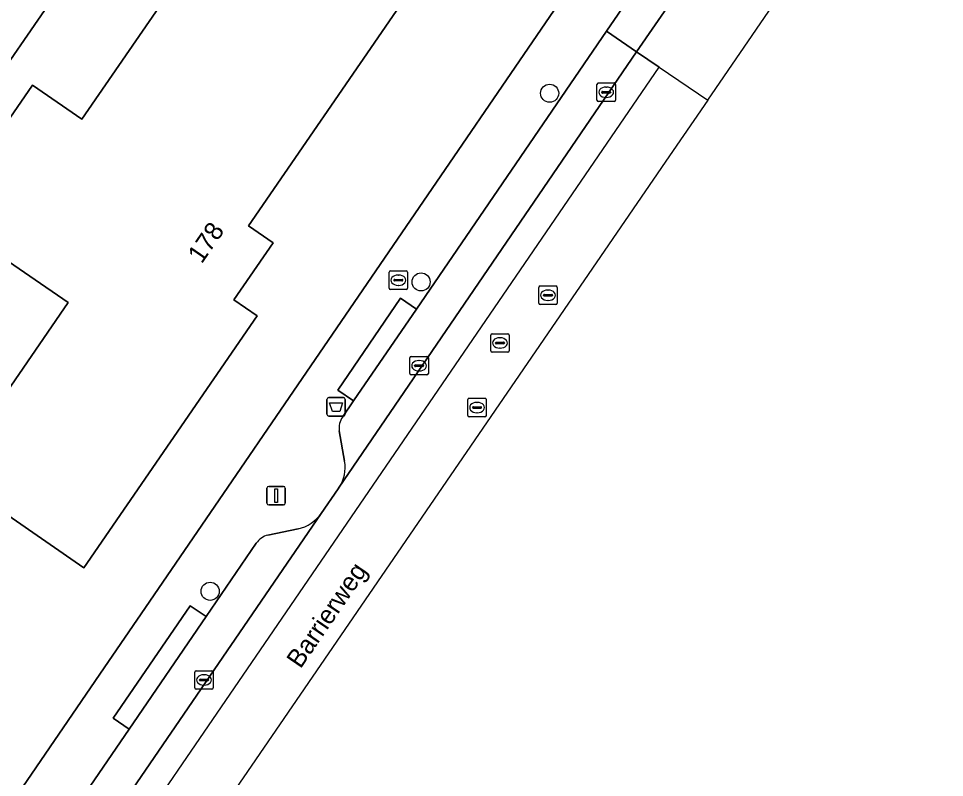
# Model space of a CAD drawing. Extents: x 159664 to 160323, y 385312 to 386115.
# Drawn here: x 160197.9 to 160248, y 385585.5 to 385626.6 of the extents above; entities that cross this region are included whole.
import ezdxf

# ---------------------------------------------------------------- set-up
doc = ezdxf.new("R2010")
doc.units = 0
for name, color, linetype in [('IMGEO_Afvalbak', 7, 'Continuous'), ('IMGEO_Boom', 7, 'Continuous'), ('IMGEO_Brandkraan', 7, 'Continuous'), ('IMGEO_Erf', 7, 'Continuous'), ('IMGEO_Kolk', 7, 'Continuous'), ('IMGEO_Lichtmast', 7, 'Continuous'), ('IMGEO_Openbare_ruimte_label', 7, 'Continuous'), ('IMGEO_Pand', 7, 'Continuous'), ('IMGEO_Pand_nummerreeks', 7, 'Continuous'), ('IMGEO_Parkeervlak_open', 7, 'Continuous'), ('IMGEO_Rijbaan_lokaal_gesloten', 7, 'Continuous'), ('IMGEO_Rijbaan_lokaal_open', 7, 'Continuous'), ('IMGEO_Rioolput', 7, 'Continuous'), ('IMGEO_Voetpad_open', 7, 'Continuous')]:
    doc.layers.add(name, color=color, linetype=linetype)

msp = doc.modelspace()

# ---------------------------------------------------------------- linework, layer by layer
at = {"layer": 'IMGEO_Afvalbak'}
for p, q in [((160214.622, 385605.183), (160214.622, 385605.983)), ((160214.622, 385605.983), (160214.622, 385605.183)), ((160214.722, 385606.083), (160215.512, 385606.083)), ((160215.512, 385606.083), (160214.722, 385606.083)), ((160215.612, 385605.983), (160215.612, 385605.183)), ((160215.612, 385605.183), (160215.612, 385605.983)), ((160215.512, 385605.083), (160214.722, 385605.083)), ((160214.722, 385605.083), (160215.512, 385605.083))]:
    msp.add_line(p, q, dxfattribs=at)
msp.add_lwpolyline([(160214.765, 385605.797), (160215.469, 385605.797), (160215.32, 385605.327), (160214.914, 385605.327), (160214.765, 385605.797)], dxfattribs=at)
for centre, start, end in [((160214.722, 385605.983), 90, 180), ((160214.722, 385605.983), 90, 180), ((160215.512, 385605.983), 0, 90), ((160215.512, 385605.983), 360, 90), ((160214.722, 385605.183), 180, 270), ((160214.722, 385605.183), 180, 270), ((160215.512, 385605.183), 270, 0), ((160215.512, 385605.183), 270, 0)]:
    msp.add_arc(centre, 0.1, start, end, dxfattribs=at)
at = {"layer": 'IMGEO_Boom'}
for centre in [(160226.666, 385622.529), (160219.712, 385612.329), (160208.305, 385595.607)]:
    msp.add_circle(centre, 0.489, dxfattribs=at)
at = {"layer": 'IMGEO_Brandkraan'}
for p, q in [((160217.983, 385611.998), (160217.983, 385612.85)), ((160218.058, 385612.924), (160218.91, 385612.924)), ((160218.285, 385612.467), (160218.683, 385612.467)), ((160218.471, 385612.704), (160218.496, 385612.704)), ((160218.984, 385612.85), (160218.984, 385611.998)), ((160218.242, 385612.418), (160218.242, 385612.43)), ((160218.68, 385612.381), (160218.282, 385612.381)), ((160218.494, 385612.144), (160218.469, 385612.144)), ((160218.726, 385612.43), (160218.726, 385612.418)), ((160218.91, 385611.924), (160218.058, 385611.924))]:
    msp.add_line(p, q, dxfattribs=at)
for points in [[(160217.983, 385611.998), (160217.983, 385612.85)], [(160218.058, 385612.924), (160218.91, 385612.924)], [(160218.984, 385612.85), (160218.984, 385611.998)], [(160218.91, 385611.924), (160218.058, 385611.924)]]:
    msp.add_lwpolyline(points, dxfattribs=at)
for centre, radius, start, end in [((160218.06, 385612.848), 0.0765, 91.552, 178.448), ((160218.06, 385612.848), 0.0765, 91.552, 178.448), ((160218.282, 385612.427), 0.0403, 85.8775, 175.7526), ((160218.687, 385612.429), 0.0386, 1.7309, 96.639), ((160218.908, 385612.848), 0.0765, 1.552, 88.448), ((160218.908, 385612.848), 0.0765, 1.552, 88.448), ((160218.06, 385612), 0.0765, 181.552, 268.448), ((160218.06, 385612), 0.0765, 181.552, 268.448), ((160218.279, 385612.417), 0.0366, 178.938, 274.7102), ((160218.683, 385612.424), 0.043, 264.8664, 352.4533), ((160218.908, 385612), 0.0765, 271.552, 358.448), ((160218.908, 385612), 0.0765, 271.552, 358.448)]:
    msp.add_arc(centre, radius, start, end, dxfattribs=at)
for centre, major_axis, ratio, start_param, end_param in [((160218.47, 385612.424), (-0.387, 0.002), 0.722429, 4.712389, 7.853982), ((160218.495, 385612.424), (-0.39, 0.002), 0.717154, 1.570796, 4.712389)]:
    msp.add_ellipse(centre, major_axis=major_axis, ratio=ratio, start_param=start_param, end_param=end_param, dxfattribs=at)
at = {"layer": 'IMGEO_Erf'}
for points in [[(160178.275, 385555.964), (160202.573, 385591.477), (160204.804, 385594.737), (160228.781, 385629.782), (160232.101, 385634.648), (160226.352, 385638.579), (160210.37, 385615.359), (160211.709, 385614.437), (160209.591, 385611.36), (160210.845, 385610.497), (160201.475, 385596.884), (160197.356, 385599.719)], [(160194.203, 385601.89), (160200.619, 385611.212), (160193.817, 385615.893), (160198.69, 385622.972), (160201.368, 385621.129), (160209.201, 385632.509), (160205.097, 385635.362), (160196.943, 385623.519)]]:
    msp.add_lwpolyline(points, dxfattribs=at)
at = {"layer": 'IMGEO_Kolk'}
for p, q in [((160229.224, 385622.157), (160229.224, 385623.009)), ((160229.299, 385623.083), (160230.151, 385623.083)), ((160230.225, 385623.009), (160230.225, 385622.157)), ((160229.483, 385622.577), (160229.483, 385622.589)), ((160229.921, 385622.54), (160229.523, 385622.54)), ((160229.526, 385622.626), (160229.924, 385622.626)), ((160229.712, 385622.863), (160229.737, 385622.863)), ((160229.967, 385622.589), (160229.967, 385622.577)), ((160230.151, 385622.083), (160229.299, 385622.083)), ((160229.735, 385622.303), (160229.71, 385622.303)), ((160219.105, 385607.375), (160219.105, 385608.227)), ((160219.18, 385608.301), (160220.032, 385608.301)), ((160219.593, 385608.081), (160219.618, 385608.081)), ((160220.106, 385608.227), (160220.106, 385607.375)), ((160219.364, 385607.795), (160219.364, 385607.807)), ((160219.802, 385607.758), (160219.404, 385607.758)), ((160219.407, 385607.844), (160219.805, 385607.844)), ((160219.616, 385607.521), (160219.591, 385607.521)), ((160219.848, 385607.807), (160219.848, 385607.795)), ((160220.032, 385607.301), (160219.18, 385607.301)), ((160207.472, 385590.39), (160207.472, 385591.242)), ((160207.547, 385591.316), (160208.399, 385591.316)), ((160207.96, 385591.096), (160207.985, 385591.096)), ((160208.473, 385591.242), (160208.473, 385590.39)), ((160207.731, 385590.81), (160207.731, 385590.822)), ((160208.169, 385590.773), (160207.771, 385590.773)), ((160207.774, 385590.859), (160208.172, 385590.859)), ((160207.983, 385590.536), (160207.958, 385590.536)), ((160208.215, 385590.822), (160208.215, 385590.81)), ((160208.399, 385590.316), (160207.547, 385590.316))]:
    msp.add_line(p, q, dxfattribs=at)
for points in [[(160229.224, 385622.157), (160229.224, 385623.009)], [(160229.299, 385623.083), (160230.151, 385623.083)], [(160230.225, 385623.009), (160230.225, 385622.157)], [(160230.151, 385622.083), (160229.299, 385622.083)], [(160219.105, 385607.375), (160219.105, 385608.227)], [(160219.18, 385608.301), (160220.032, 385608.301)], [(160220.106, 385608.227), (160220.106, 385607.375)], [(160220.032, 385607.301), (160219.18, 385607.301)], [(160207.472, 385590.39), (160207.472, 385591.242)], [(160207.547, 385591.316), (160208.399, 385591.316)], [(160208.473, 385591.242), (160208.473, 385590.39)], [(160208.399, 385590.316), (160207.547, 385590.316)]]:
    msp.add_lwpolyline(points, dxfattribs=at)
for centre, radius, start, end in [((160229.301, 385623.007), 0.0765, 91.552, 178.448), ((160229.301, 385623.007), 0.0765, 91.552, 178.448), ((160230.149, 385623.007), 0.0765, 1.552, 88.448), ((160230.149, 385623.007), 0.0765, 1.552, 88.448), ((160229.523, 385622.586), 0.0403, 85.8775, 175.7526), ((160229.52, 385622.576), 0.0366, 178.938, 274.7102), ((160229.924, 385622.583), 0.043, 264.8664, 352.4533), ((160229.928, 385622.588), 0.0386, 1.7309, 96.639), ((160229.301, 385622.159), 0.0765, 181.552, 268.448), ((160229.301, 385622.159), 0.0765, 181.552, 268.448), ((160230.149, 385622.159), 0.0765, 271.552, 358.448), ((160230.149, 385622.159), 0.0765, 271.552, 358.448), ((160219.182, 385608.225), 0.0765, 91.552, 178.448), ((160219.182, 385608.225), 0.0765, 91.552, 178.448), ((160220.03, 385608.225), 0.0765, 1.552, 88.448), ((160220.03, 385608.225), 0.0765, 1.552, 88.448), ((160219.404, 385607.804), 0.0403, 85.8775, 175.7526), ((160219.401, 385607.794), 0.0366, 178.938, 274.7102), ((160219.805, 385607.801), 0.043, 264.8664, 352.4533), ((160219.809, 385607.806), 0.0386, 1.7309, 96.639), ((160219.182, 385607.377), 0.0765, 181.552, 268.448), ((160219.182, 385607.377), 0.0765, 181.552, 268.448), ((160220.03, 385607.377), 0.0765, 271.552, 358.448), ((160220.03, 385607.377), 0.0765, 271.552, 358.448), ((160207.549, 385591.24), 0.0765, 91.552, 178.448), ((160207.549, 385591.24), 0.0765, 91.552, 178.448), ((160208.397, 385591.24), 0.0765, 1.552, 88.448), ((160208.397, 385591.24), 0.0765, 1.552, 88.448), ((160207.771, 385590.819), 0.0403, 85.8775, 175.7526), ((160207.768, 385590.809), 0.0366, 178.938, 274.7102), ((160208.172, 385590.816), 0.043, 264.8664, 352.4533), ((160208.176, 385590.821), 0.0386, 1.7309, 96.639), ((160207.549, 385590.392), 0.0765, 181.552, 268.448), ((160207.549, 385590.392), 0.0765, 181.552, 268.448), ((160208.397, 385590.392), 0.0765, 271.552, 358.448), ((160208.397, 385590.392), 0.0765, 271.552, 358.448)]:
    msp.add_arc(centre, radius, start, end, dxfattribs=at)
for centre, major_axis, ratio, start_param, end_param in [((160229.711, 385622.583), (-0.387, 0.002), 0.722429, 4.712389, 7.853982), ((160229.736, 385622.583), (-0.39, 0.002), 0.717154, 1.570796, 4.712389), ((160219.592, 385607.801), (-0.387, 0.002), 0.722429, 4.712389, 7.853982), ((160219.617, 385607.801), (-0.39, 0.002), 0.717154, 1.570796, 4.712389), ((160207.959, 385590.816), (-0.387, 0.002), 0.722429, 4.712389, 7.853982), ((160207.984, 385590.816), (-0.39, 0.002), 0.717154, 1.570796, 4.712389)]:
    msp.add_ellipse(centre, major_axis=major_axis, ratio=ratio, start_param=start_param, end_param=end_param, dxfattribs=at)
at = {"layer": 'IMGEO_Lichtmast'}
for p, q in [((160211.378, 385600.375), (160211.378, 385601.175)), ((160211.378, 385601.175), (160211.378, 385600.375)), ((160211.478, 385601.275), (160212.268, 385601.275)), ((160212.268, 385601.275), (160211.478, 385601.275)), ((160212.368, 385601.175), (160212.368, 385600.375)), ((160212.368, 385600.375), (160212.368, 385601.175)), ((160212.268, 385600.275), (160211.478, 385600.275)), ((160211.478, 385600.275), (160212.268, 385600.275))]:
    msp.add_line(p, q, dxfattribs=at)
msp.add_lwpolyline([(160211.798, 385601.15), (160211.948, 385601.15), (160211.948, 385600.4), (160211.798, 385600.4), (160211.798, 385601.15)], dxfattribs=at)
for centre, start, end in [((160211.478, 385601.175), 90, 180), ((160211.478, 385601.175), 90, 180), ((160212.268, 385601.175), 0, 90), ((160212.268, 385601.175), 360, 90), ((160211.478, 385600.375), 180, 270), ((160211.478, 385600.375), 180, 270), ((160212.268, 385600.375), 270, 0), ((160212.268, 385600.375), 270, 0)]:
    msp.add_arc(centre, 0.1, start, end, dxfattribs=at)
at = {"layer": 'IMGEO_Pand'}
for points in [[(160197.356, 385599.719), (160201.475, 385596.884), (160210.845, 385610.497), (160209.591, 385611.36), (160211.709, 385614.437), (160210.37, 385615.359), (160226.352, 385638.579), (160222.234, 385641.414), (160217.549, 385644.638), (160210.632, 385634.588), (160206.472, 385637.452), (160210.157, 385642.806), (160205.116, 385646.276), (160204.231, 385645.558), (160201.955, 385648.447), (160179.521, 385630.759)], [(160196.943, 385623.519), (160205.097, 385635.362), (160209.201, 385632.509), (160201.368, 385621.129), (160198.69, 385622.972), (160193.817, 385615.893), (160200.619, 385611.212), (160194.203, 385601.89)]]:
    msp.add_lwpolyline(points, dxfattribs=at)
at = {"layer": 'IMGEO_Parkeervlak_open'}
msp.add_lwpolyline([(160236.414, 385632.08), (160234.747, 385633.204), (160229.746, 385625.888), (160231.373, 385624.758)], close=True, dxfattribs=at)
for points in [[(160215.29, 385601.23), (160231.373, 385624.758), (160229.746, 385625.888), (160219.461, 385610.857), (160216.064, 385605.904), (160215.467, 385605.028)], [(160215.291, 385604.285), (160215.575, 385602.641)], [(160179.07, 385548.372), (160214.312, 385599.817)], [(160213.064, 385598.983), (160211.433, 385598.646)], [(160210.8, 385598.206), (160208.094, 385594.237)], [(160208.094, 385594.237), (160203.917, 385588.151)], [(160203.917, 385588.151), (160184.214, 385559.396)]]:
    msp.add_lwpolyline(points, dxfattribs=at)
for centre, radius, start, end in [((160216.316, 385604.434), 1.036, 145.0553, 188.2918), ((160213.65, 385602.295), 1.955, 326.9834, 10.1782), ((160212.614, 385601.007), 2.073, 282.5296, 324.9775), ((160211.677, 385597.62), 1.055, 103.3683, 146.2383)]:
    msp.add_arc(centre, radius, start, end, dxfattribs=at)
at = {"layer": 'IMGEO_Rijbaan_lokaal_gesloten'}
for points in [[(160232.588, 385623.938), (160231.373, 385624.758), (160215.29, 385601.23), (160215.227, 385601.138), (160214.312, 385599.817), (160179.07, 385548.372), (160180.264, 385547.548)], [(160182.815, 385545.787), (160180.264, 385547.548), (160232.588, 385623.938), (160235.223, 385622.158), (160233.158, 385619.148), (160186.379, 385550.98)]]:
    msp.add_lwpolyline(points, close=True, dxfattribs=at)
at = {"layer": 'IMGEO_Rijbaan_lokaal_open'}
msp.add_lwpolyline([(160235.223, 385622.158), (160240.259, 385629.497), (160237.653, 385631.248), (160236.414, 385632.08), (160231.373, 385624.758), (160232.588, 385623.938)], close=True, dxfattribs=at)
at = {"layer": 'IMGEO_Rioolput'}
for p, q in [((160226.08, 385611.184), (160226.08, 385612.036)), ((160226.155, 385612.11), (160227.007, 385612.11)), ((160227.081, 385612.036), (160227.081, 385611.184)), ((160226.339, 385611.604), (160226.339, 385611.616)), ((160226.777, 385611.567), (160226.379, 385611.567)), ((160226.382, 385611.653), (160226.78, 385611.653)), ((160226.568, 385611.89), (160226.593, 385611.89)), ((160226.823, 385611.616), (160226.823, 385611.604)), ((160227.007, 385611.11), (160226.155, 385611.11)), ((160226.591, 385611.33), (160226.566, 385611.33)), ((160223.477, 385608.604), (160223.477, 385609.456)), ((160223.552, 385609.53), (160224.404, 385609.53)), ((160224.478, 385609.456), (160224.478, 385608.604)), ((160223.736, 385609.024), (160223.736, 385609.036)), ((160224.174, 385608.987), (160223.776, 385608.987)), ((160223.779, 385609.073), (160224.177, 385609.073)), ((160223.965, 385609.31), (160223.99, 385609.31)), ((160224.22, 385609.036), (160224.22, 385609.024)), ((160224.404, 385608.53), (160223.552, 385608.53)), ((160223.988, 385608.75), (160223.963, 385608.75)), ((160222.241, 385605.114), (160222.241, 385605.966)), ((160222.316, 385606.04), (160223.168, 385606.04)), ((160223.242, 385605.966), (160223.242, 385605.114)), ((160222.5, 385605.534), (160222.5, 385605.546)), ((160222.938, 385605.497), (160222.54, 385605.497)), ((160222.543, 385605.583), (160222.941, 385605.583)), ((160222.729, 385605.82), (160222.754, 385605.82)), ((160222.984, 385605.546), (160222.984, 385605.534)), ((160223.168, 385605.04), (160222.316, 385605.04)), ((160222.752, 385605.26), (160222.727, 385605.26))]:
    msp.add_line(p, q, dxfattribs=at)
for points in [[(160226.08, 385611.184), (160226.08, 385612.036)], [(160226.155, 385612.11), (160227.007, 385612.11)], [(160227.081, 385612.036), (160227.081, 385611.184)], [(160227.007, 385611.11), (160226.155, 385611.11)], [(160223.477, 385608.604), (160223.477, 385609.456)], [(160223.552, 385609.53), (160224.404, 385609.53)], [(160224.478, 385609.456), (160224.478, 385608.604)], [(160224.404, 385608.53), (160223.552, 385608.53)], [(160222.241, 385605.114), (160222.241, 385605.966)], [(160222.316, 385606.04), (160223.168, 385606.04)], [(160223.242, 385605.966), (160223.242, 385605.114)], [(160223.168, 385605.04), (160222.316, 385605.04)]]:
    msp.add_lwpolyline(points, dxfattribs=at)
for centre, radius, start, end in [((160226.157, 385612.034), 0.0765, 91.552, 178.448), ((160226.157, 385612.034), 0.0765, 91.552, 178.448), ((160227.005, 385612.034), 0.0765, 1.552, 88.448), ((160227.005, 385612.034), 0.0765, 1.552, 88.448), ((160226.379, 385611.613), 0.0403, 85.8775, 175.7526), ((160226.376, 385611.603), 0.0366, 178.938, 274.7102), ((160226.78, 385611.61), 0.043, 264.8664, 352.4533), ((160226.784, 385611.615), 0.0386, 1.7309, 96.639), ((160226.157, 385611.186), 0.0765, 181.552, 268.448), ((160226.157, 385611.186), 0.0765, 181.552, 268.448), ((160227.005, 385611.186), 0.0765, 271.552, 358.448), ((160227.005, 385611.186), 0.0765, 271.552, 358.448), ((160223.554, 385609.454), 0.0765, 91.552, 178.448), ((160223.554, 385609.454), 0.0765, 91.552, 178.448), ((160224.402, 385609.454), 0.0765, 1.552, 88.448), ((160224.402, 385609.454), 0.0765, 1.552, 88.448), ((160223.776, 385609.033), 0.0403, 85.8775, 175.7526), ((160223.773, 385609.023), 0.0366, 178.938, 274.7102), ((160224.177, 385609.03), 0.043, 264.8664, 352.4533), ((160224.181, 385609.035), 0.0386, 1.7309, 96.639), ((160223.554, 385608.606), 0.0765, 181.552, 268.448), ((160223.554, 385608.606), 0.0765, 181.552, 268.448), ((160224.402, 385608.606), 0.0765, 271.552, 358.448), ((160224.402, 385608.606), 0.0765, 271.552, 358.448), ((160222.318, 385605.964), 0.0765, 91.552, 178.448), ((160222.318, 385605.964), 0.0765, 91.552, 178.448), ((160223.166, 385605.964), 0.0765, 1.552, 88.448), ((160223.166, 385605.964), 0.0765, 1.552, 88.448), ((160222.54, 385605.543), 0.0403, 85.8775, 175.7526), ((160222.537, 385605.533), 0.0366, 178.938, 274.7102), ((160222.941, 385605.54), 0.043, 264.8664, 352.4533), ((160222.945, 385605.545), 0.0386, 1.7309, 96.639), ((160222.318, 385605.116), 0.0765, 181.552, 268.448), ((160222.318, 385605.116), 0.0765, 181.552, 268.448), ((160223.166, 385605.116), 0.0765, 271.552, 358.448), ((160223.166, 385605.116), 0.0765, 271.552, 358.448)]:
    msp.add_arc(centre, radius, start, end, dxfattribs=at)
for centre, major_axis, ratio, start_param, end_param in [((160226.567, 385611.61), (-0.387, 0.002), 0.722429, 4.712389, 7.853982), ((160226.592, 385611.61), (-0.39, 0.002), 0.717154, 1.570796, 4.712389), ((160223.964, 385609.03), (-0.387, 0.002), 0.722429, 4.712389, 7.853982), ((160223.989, 385609.03), (-0.39, 0.002), 0.717154, 1.570796, 4.712389), ((160222.728, 385605.54), (-0.387, 0.002), 0.722429, 4.712389, 7.853982), ((160222.753, 385605.54), (-0.39, 0.002), 0.717154, 1.570796, 4.712389)]:
    msp.add_ellipse(centre, major_axis=major_axis, ratio=ratio, start_param=start_param, end_param=end_param, dxfattribs=at)
at = {"layer": 'IMGEO_Voetpad_open'}
for points in [[(160215.467, 385605.028), (160216.064, 385605.904), (160215.208, 385606.488), (160218.599, 385611.45), (160219.461, 385610.857), (160229.746, 385625.888), (160234.747, 385633.204), (160235.362, 385634.046), (160234.512, 385634.645), (160236.961, 385638.254), (160237.832, 385637.679), (160240.217, 385641.145), (160239.343, 385641.729), (160241.888, 385645.434), (160242.752, 385644.842), (160244.957, 385648.047), (160244.093, 385648.659), (160246.655, 385652.36), (160247.504, 385651.778), (160249.279, 385654.209), (160248.42, 385654.818)], [(160245.33, 385653.937), (160242.855, 385650.375), (160232.683, 385635.499), (160232.175, 385634.756), (160232.101, 385634.648), (160228.781, 385629.782), (160204.804, 385594.737), (160202.573, 385591.477), (160178.275, 385555.964), (160177.701, 385555.126), (160176.002, 385552.634), (160149.713, 385514.246), (160148.995, 385513.197), (160142.133, 385503.177), (160129.756, 385485.105), (160128.186, 385482.814)], [(160215.575, 385602.641), (160215.291, 385604.285)], [(160214.312, 385599.817), (160215.227, 385601.138), (160215.29, 385601.23)], [(160211.433, 385598.646), (160213.064, 385598.983)], [(160171.768, 385541.228), (160177.428, 385549.488), (160176.546, 385550.067), (160183.342, 385559.985), (160184.214, 385559.396), (160203.917, 385588.151), (160203.06, 385588.748), (160207.226, 385594.829), (160208.094, 385594.237), (160210.8, 385598.206)]]:
    msp.add_lwpolyline(points, dxfattribs=at)
for points in [[(160219.461, 385610.857), (160218.599, 385611.45), (160215.208, 385606.488), (160216.064, 385605.904)], [(160208.094, 385594.237), (160207.226, 385594.829), (160203.06, 385588.748), (160203.917, 385588.151)]]:
    msp.add_lwpolyline(points, close=True, dxfattribs=at)
for centre, radius, start, end in [((160216.316, 385604.434), 1.036, 145.0553, 188.2918), ((160213.65, 385602.295), 1.955, 326.9834, 10.1782), ((160212.614, 385601.007), 2.073, 282.5296, 324.9775), ((160211.677, 385597.62), 1.055, 103.3683, 146.2383)]:
    msp.add_arc(centre, radius, start, end, dxfattribs=at)

# ---------------------------------------------------------------- texts
at = {"layer": 'IMGEO_Openbare_ruimte_label'}
msp.add_text('Barrierweg', height=1, rotation=55.6421, dxfattribs=at).set_placement((160213.191, 385591.383))
at = {"layer": 'IMGEO_Pand_nummerreeks'}
msp.add_text('178', height=1, rotation=55.4591, dxfattribs=at).set_placement((160207.847, 385613.271))

doc.saveas('drawing.dxf')
